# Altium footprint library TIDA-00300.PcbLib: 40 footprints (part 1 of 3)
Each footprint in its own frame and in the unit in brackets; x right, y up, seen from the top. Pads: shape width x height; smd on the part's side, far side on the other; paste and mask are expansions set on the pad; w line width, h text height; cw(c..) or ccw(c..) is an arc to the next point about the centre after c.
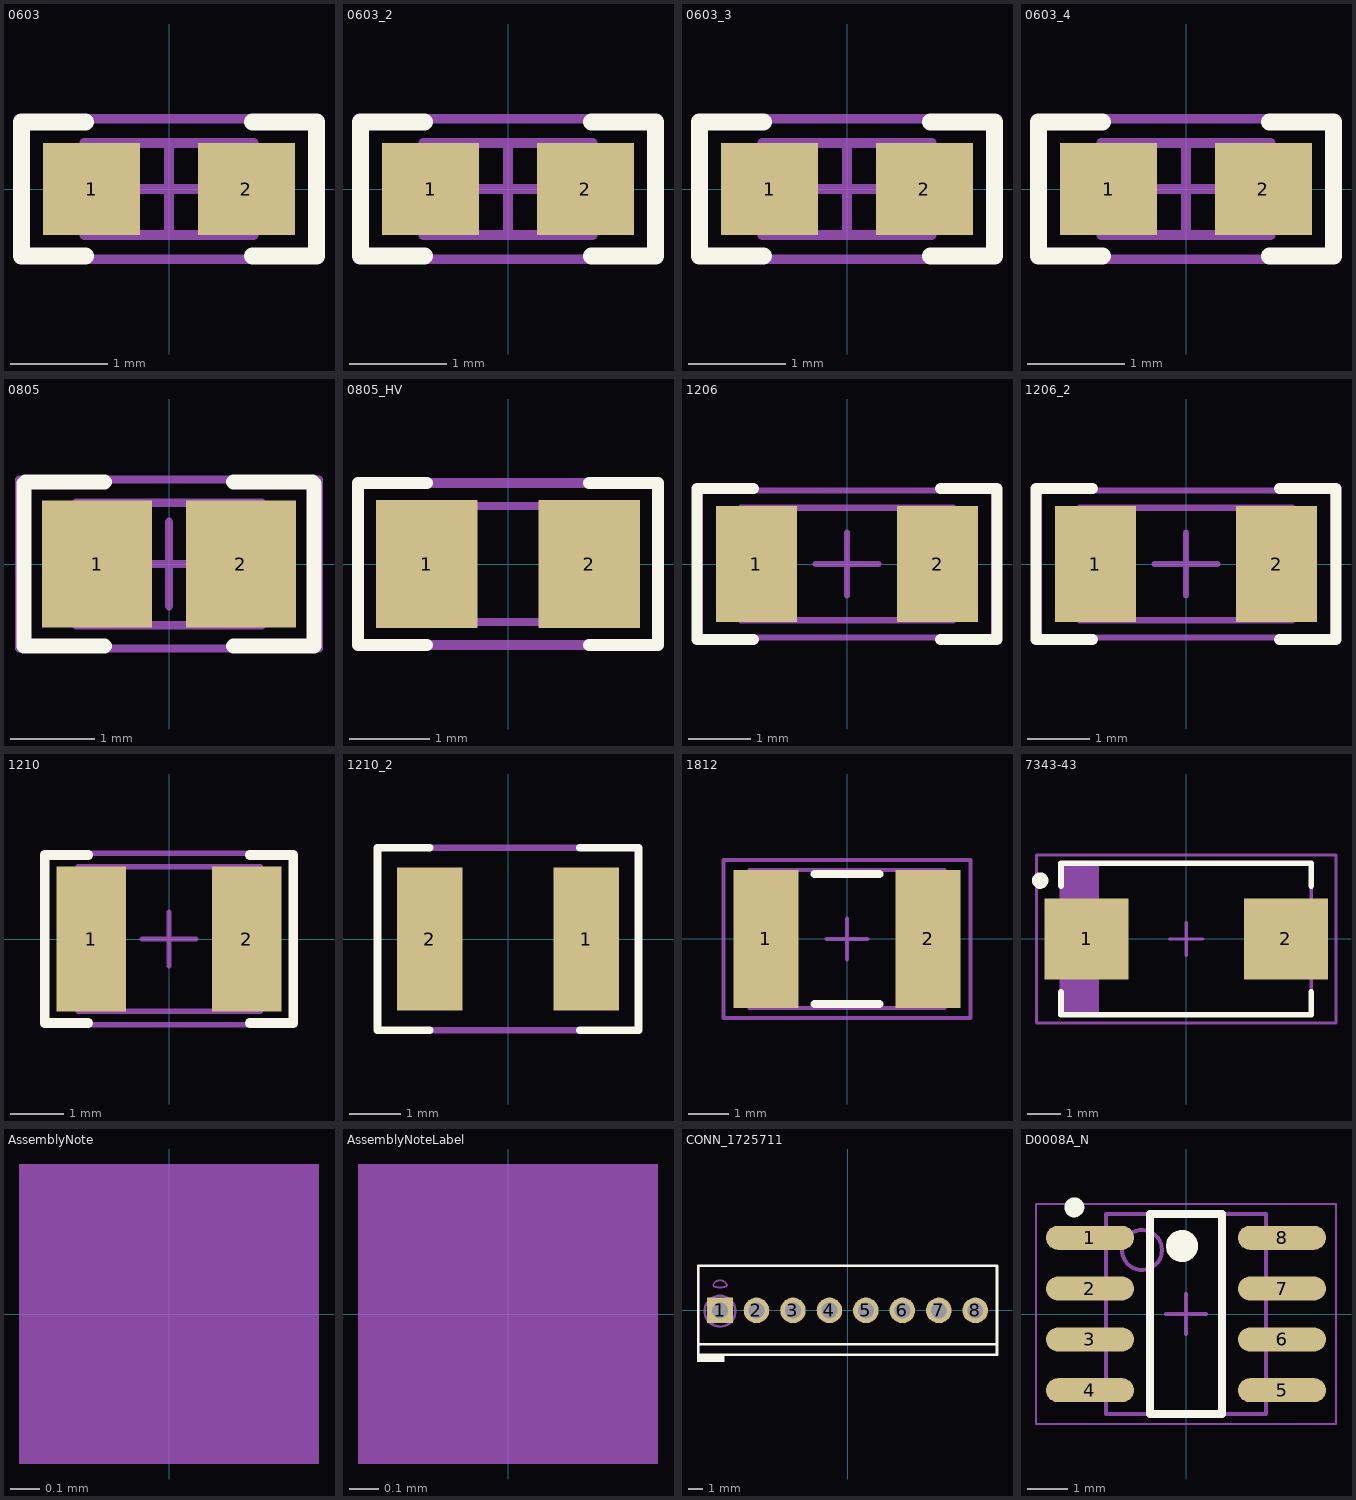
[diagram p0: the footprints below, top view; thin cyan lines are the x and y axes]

## 0603 [mm] "0603 from SM-752 data"
height 0.85
pads (2):
  rect 1x0.95 smd: 1(-0.8,0) 2(0.8,0)
Top Overlay:
  lines w0.178: -0.864,-0.691 -1.524,-0.691 -1.524,0.693 -0.864,0.693 ; 0.864,-0.691 1.524,-0.691 1.524,0.693 0.864,0.693
Mechanical 5:
  lines w0.1: -1.55,-0.725 1.55,-0.725 1.55,0.725 -1.55,0.725 -1.55,-0.725
  text ".Designator" at -1.067,-0.33 h0.76
Mechanical 13:
  lines w0.1: -0.55,-0.475 -0.55,0.475 ; 0.55,-0.475 0.55,0.475 ; -0.875,-0.475 -0.875,0.475 0.875,0.475 0.875,-0.475 -0.875,-0.475
Mechanical 15:
  lines w0.1: -0.475,0 0.475,0 ; 0,-0.475 0,0.475 ; -1.55,-0.725 -1.55,0.725 1.55,0.725 1.55,-0.725 -1.55,-0.725
3D body: height 0.85, standoff 0, extent 0.551,-0.474 0.874,0.474
3D body: height 0.85, standoff 0, extent -0.549,-0.474 0.549,0.474
3D body: height 0.85, standoff 0, extent -0.874,-0.474 -0.551,0.474

## 0603_2 [mm]
pads (2):
  rect 1x0.95 smd: 1(-0.8,0) 2(0.8,0)
Top Overlay:
  lines w0.178: -0.864,-0.691 -1.524,-0.691 -1.524,0.693 -0.864,0.693 ; 0.864,-0.691 1.524,-0.691 1.524,0.693 0.864,0.693
Mechanical 5:
  lines w0.1: -1.55,-0.725 -1.55,0.725 1.55,0.725 1.55,-0.725 -1.55,-0.725
  text ".Designator" at 0.914,0.406 h0.76
Mechanical 13:
  lines w0.1: -0.55,-0.475 -0.55,0.475 ; 0.55,-0.475 0.55,0.475 ; -0.875,-0.475 0.875,-0.475 0.875,0.475 -0.875,0.475 -0.875,-0.475
Mechanical 15:
  lines w0.1: -0.475,0 0.475,0 ; 0,-0.475 0,0.475 ; -1.55,-0.725 1.55,-0.725 1.55,0.725 -1.55,0.725 -1.55,-0.725
3D body: height 0.85, standoff 0, extent -0.874,-0.474 -0.551,0.474
3D body: height 0.85, standoff 0, extent -0.549,-0.474 0.549,0.474
3D body: height 0.85, standoff 0, extent 0.551,-0.474 0.874,0.474

## 0603_3 [mm]
pads (2):
  rect 1x0.95 smd: 1(-0.8,0) 2(0.8,0)
Top Overlay:
  lines w0.178: -0.864,-0.691 -1.524,-0.691 -1.524,0.693 -0.864,0.693 ; 0.864,-0.691 1.524,-0.691 1.524,0.693 0.864,0.693
Mechanical 5:
  lines w0.1: -1.55,-0.725 1.55,-0.725 1.55,0.725 -1.55,0.725 -1.55,-0.725
  text ".Designator" at -1.143,-0.381 h0.76
Mechanical 13:
  lines w0.1: -0.55,-0.475 -0.55,0.475 ; 0.55,-0.475 0.55,0.475 ; -0.875,-0.475 -0.875,0.475 0.875,0.475 0.875,-0.475 -0.875,-0.475
Mechanical 15:
  lines w0.1: -0.475,0 0.475,0 ; 0,-0.475 0,0.475 ; -1.55,-0.725 -1.55,0.725 1.55,0.725 1.55,-0.725 -1.55,-0.725
3D body: height 0.85, standoff 0, extent 0.551,-0.474 0.874,0.474
3D body: height 0.85, standoff 0, extent -0.549,-0.474 0.549,0.474
3D body: height 0.85, standoff 0, extent -0.874,-0.474 -0.551,0.474

## 0603_4 [mm]
pads (2):
  rect 1x0.95 smd: 1(-0.8,0) 2(0.8,0)
Top Overlay:
  lines w0.178: -0.864,-0.691 -1.524,-0.691 -1.524,0.693 -0.864,0.693 ; 0.864,-0.691 1.524,-0.691 1.524,0.693 0.864,0.693
Mechanical 5:
  lines w0.1: -1.55,-0.725 -1.55,0.725 1.55,0.725 1.55,-0.725 -1.55,-0.725
  text ".Designator" at -1.016,-0.356 h0.76
Mechanical 13:
  lines w0.1: -0.55,-0.475 -0.55,0.475 ; 0.55,-0.475 0.55,0.475 ; -0.875,-0.475 0.875,-0.475 0.875,0.475 -0.875,0.475 -0.875,-0.475
Mechanical 15:
  lines w0.1: -0.475,0 0.475,0 ; 0,-0.475 0,0.475 ; -1.55,-0.725 1.55,-0.725 1.55,0.725 -1.55,0.725 -1.55,-0.725
3D body: height 0.85, standoff 0, extent -0.874,-0.474 -0.551,0.474
3D body: height 0.85, standoff 0, extent -0.549,-0.474 0.549,0.474
3D body: height 0.85, standoff 0, extent 0.551,-0.474 0.874,0.474

## 0805 [mm] "0805 from SM-752 data"
height 1.1
pads (2):
  rect 1.3x1.5 smd: 1(-0.85,0) 2(0.85,0)
Top Overlay:
  lines w0.178: -0.762,-0.968 -1.717,-0.968 -1.717,0.95 -1.699,0.968 -0.762,0.968 ; 0.762,-0.968 1.717,-0.968 1.717,0.95 1.699,0.968 0.762,0.968
Mechanical 5:
  lines w0.1: -1.775,-1 -1.775,1 1.775,1 1.775,-1 -1.775,-1
  text ".Designator" at -1.143,-0.381 h0.76
Mechanical 13:
  lines w0.1: -0.65,-0.725 -0.65,0.725 ; 0.65,-0.725 0.65,0.725 ; -1.1,-0.725 -1.1,0.725 1.1,0.725 1.1,-0.725 -1.1,-0.725
Mechanical 15:
  lines w0.1: -0.5,0 0.5,0 ; 0,-0.5 0,0.5 ; -1.775,-1 -1.775,1 1.775,1 1.775,-1 -1.775,-1
3D body: height 1.1, standoff 0, extent 0.651,-0.724 1.099,0.724
3D body: height 1.1, standoff 0, extent -0.649,-0.724 0.649,0.724
3D body: height 1.1, standoff 0, extent -1.099,-0.724 -0.651,0.724

## 0805_HV [mil] "0805 with 30mil clearance between pads"
height 43.31
pads (2):
  rect 50x63 smd: 1(-40,0) 2(40,0)
Top Overlay:
  lines w6: -40,-40 -74,-40 -74,0 -74,40 -40,40 ; 40,-40 74,-40 74,0 74,40 40,40
Mechanical 5:
  lines w5: -74,-40 74,-40 74,40 -74,40 -74,-40
  text ".Designator" at -38,-18 h30
Mechanical 13:
  lines w3.94: -25.59,-28.54 -25.59,28.54 ; 25.59,-28.54 25.59,28.54 ; -43.31,-28.54 -43.31,28.54 43.31,28.54 43.31,-28.54 -43.31,-28.54
3D body: height 43.31, standoff 0, extent 25.61,-28.52 43.29,28.52
3D body: height 43.31, standoff 0, extent -25.57,-28.52 25.57,28.52
3D body: height 43.31, standoff 0, extent -43.29,-28.52 -25.61,28.52

## 1206 [mm] "1206 from SM-752 data"
height 1.35
pads (2):
  rect 1.3x1.85 smd: 1(-1.45,0) 2(1.45,0)
Top Overlay:
  lines w0.178: -1.5,-1.21 -2.4,-1.21 -2.4,1.21 -1.5,1.21 ; 1.5,-1.21 2.4,-1.21 2.4,1.21 1.5,1.21
Mechanical 5:
  lines w0.1: -1.7,-0.9 1.7,-0.9 1.7,0.9 -1.7,0.9 -1.7,-0.9
  text ".Designator" at 1.194,0.305 h0.76
Mechanical 13:
  lines w0.1: -1.2,-0.9 -1.2,0.9 ; 1.2,-0.9 1.2,0.9 ; -1.7,-0.9 1.7,-0.9 1.7,0.9 -1.7,0.9 -1.7,-0.9
Mechanical 15:
  lines w0.1: -0.5,0 0.5,0 ; 0,-0.5 0,0.5 ; -2.35,-1.175 2.35,-1.175 2.35,1.175 -2.35,1.175 -2.35,-1.175
3D body: height 1.35, standoff 0, extent -1.699,-0.899 -1.201,0.899
3D body: height 1.35, standoff 0, extent -1.199,-0.899 1.199,0.899
3D body: height 1.35, standoff 0, extent 1.201,-0.899 1.699,0.899

## 1206_2 [mm]
pads (2):
  rect 1.3x1.85 smd: 1(-1.45,0) 2(1.45,0)
Top Overlay:
  lines w0.178: -1.5,-1.21 -2.4,-1.21 -2.4,1.21 -1.5,1.21 ; 1.5,-1.21 2.4,-1.21 2.4,1.21 1.5,1.21
Mechanical 5:
  lines w0.1: -1.7,-0.9 1.7,-0.9 1.7,0.9 -1.7,0.9 -1.7,-0.9
  text ".Designator" at -0.635,-0.406 h0.81
Mechanical 13:
  lines w0.1: -1.2,-0.9 -1.2,0.9 ; 1.2,-0.9 1.2,0.9 ; -1.7,-0.9 1.7,-0.9 1.7,0.9 -1.7,0.9 -1.7,-0.9
Mechanical 15:
  lines w0.1: -0.5,0 0.5,0 ; 0,-0.5 0,0.5 ; -2.35,-1.175 2.35,-1.175 2.35,1.175 -2.35,1.175 -2.35,-1.175
3D body: height 1.35, standoff 0, extent -1.699,-0.899 -1.201,0.899
3D body: height 1.35, standoff 0, extent -1.199,-0.899 1.199,0.899
3D body: height 1.35, standoff 0, extent 1.201,-0.899 1.699,0.899

## 1210 [mm] "1210 from SM-752 data"
height 1.35
pads (2):
  rect 1.3x2.7 smd: 1(-1.45,0) 2(1.45,0)
Top Overlay:
  lines w0.178: -1.511,-1.568 -2.316,-1.568 -2.316,1.568 -1.511,1.568 ; 1.511,-1.568 2.316,-1.568 2.316,1.568 1.511,1.568
Mechanical 5:
  lines w0.1: -1.7,-1.35 -1.7,1.35 1.7,1.35 1.7,-1.35 -1.7,-1.35
  text ".Designator" at -0.584,-0.305 h0.76
Mechanical 13:
  lines w0.1: -1.2,-1.35 -1.2,1.35 ; 1.2,-1.35 1.2,1.35 ; -1.7,-1.35 1.7,-1.35 1.7,1.35 -1.7,1.35 -1.7,-1.35
Mechanical 15:
  lines w0.1: -0.5,0 0.5,0 ; 0,-0.5 0,0.5 ; -2.35,-1.6 2.35,-1.6 2.35,1.6 -2.35,1.6 -2.35,-1.6
3D body: height 1.35, standoff 0, extent 1.201,-1.349 1.699,1.349
3D body: height 1.35, standoff 0, extent -1.199,-1.349 1.199,1.349
3D body: height 1.35, standoff 0, extent -1.699,-1.349 -1.201,1.349

## 1210_2 [mil]
pads (2):
  rect 50x110 smd: 1(60,0) 2(-60,0)
Top Overlay:
  lines w6: -60,-70 -100,-70 -100,70 -60,70 ; 55,-70 100,-70 100,70 55,70
Mechanical 5:
  lines w5: -100,-70 100,-70 100,70 -100,70 -100,-70
  text ".Designator" at 40,20 h30

## 1812 [mm]
height 1.35
pads (2):
  rect 1.6x3.4 smd: 1(-2,0) 2(2,0)
Top Overlay:
  lines w0.2: -0.8,-1.6 0.8,-1.6 ; -0.8,1.6 0.8,1.6
Mechanical 5:
  lines w0.1: -2.4,-1.7 -2.4,1.7 2.4,1.7 2.4,-1.7 -2.4,-1.7
  text ".Designator" at 0.889,0.635 h1.02
Mechanical 13:
  lines w0.1: -1.9,-1.7 -1.9,1.7 ; 1.9,-1.7 1.9,1.7 ; -2.4,-1.7 2.4,-1.7 2.4,1.7 -2.4,1.7 -2.4,-1.7
Mechanical 15:
  lines w0.1: -0.5,0 0.5,0 ; 0,-0.5 0,0.5 ; -3.05,-1.95 3.05,-1.95 3.05,1.95 -3.05,1.95 -3.05,-1.95
3D body: height 1.35, standoff 0, extent 1.901,-1.699 2.399,1.699
3D body: height 1.35, standoff 0, extent -1.899,-1.699 1.899,1.699
3D body: height 1.35, standoff 0, extent -2.399,-1.699 -1.901,1.699

## 7343-43 [mm] "Medium density IPC based on Kemet T495 series"
height 4.3
pads (2):
  rect 2.55x2.45 smd: 1(-3.025,0) 2(3.025,0)
Top Overlay:
  circle w0.25: c-4.439,1.775 r0.125
  lines w0.178: -3.8,-1.614 -3.8,-2.3 3.8,-2.3 3.8,-1.614 ; -3.8,1.614 -3.8,2.3 3.8,2.3 3.8,1.614
Mechanical 5:
  rectangle: -3.8,-2.3 -2.7,2.3
  lines w0.1: -2.7,-2.3 -2.7,2.3 ; -3.8,-2.3 -3.8,2.3 3.8,2.3 3.8,-2.3 -3.8,-2.3
  text ".Designator" at -1.194,-0.457 h1.02
Mechanical 15:
  lines w0.1: -0.5,0 0.5,0 ; 0,-0.5 0,0.5 ; -4.55,-2.55 -4.55,2.55 4.55,2.55 4.55,-2.55 -4.55,-2.55
3D body: height 4.3, standoff 4.3, extent -3.799,-2.299 -2.701,2.299
3D body: height 4.3, standoff 0, extent -3.8,-2.3 3.8,2.3

## AssemblyNote [mm] "Assembly Note"
Mechanical 5:
  rectangle: -0.508,-0.508 0.508,0.508
  text ".Comment" at 1.143,-0.508 h0.76
  text ".Designator" at -4.191,-0.508 h0.76

## AssemblyNoteLabel [mm] "Assembly Note for PCB Labels"
Mechanical 5:
  rectangle: -0.508,-0.508 0.508,0.508
  text "Install label in silkscreened box after final wash.  Text shall be 8 pt font.  Text shall be per the Label Table in the PDF schematic." at 1.651,-0.457 h0.76
  text ".Designator" at -3.683,-0.457 h0.76

## CONN_1725711 [mm] "Phoenix Contact"
height 13.8
pads (8):
  rect 1.78x1.78 hole 1.1: 1(-8.89,0)
  round 1.78 hole 1.1: 2(-6.35,0) 3(-3.81,0) 4(-1.27,0) 5(1.27,0) 6(3.81,0) 7(6.35,0) 8(8.89,0)
Top Overlay:
  rectangle: -10.493,-3.6 -8.588,-3.1
  lines w0.178: -10.39,-2.361 10.39,-2.361 ; -10.404,-3.1 10.4,-3.1 10.4,3.1 -10.398,3.1 -10.404,-3.1
Mechanical 5:
  lines w0.127: -10.39,-2.361 -10.39,-2.8 -10.39,-3.1 10.39,-3.1 10.39,-2.8 10.39,-2.361 ; -10.39,-2.361 -10.39,-1.51 -10.39,-1.22 -10.39,1.132 -10.39,1.417 -10.39,3.1 10.39,3.1 10.39,1.417 10.39,1.132 10.39,-1.22 10.39,-1.51 10.39,-2.361 ; -10.39,-2.361 10.39,-2.361 ; -9.788,-0.594 cw(c-8.89,-0.05) -8.89,1 cw(c-8.89,-0.05) -8.346,0.848 ; -9.788,-0.594 ccw(c-8.89,-0.05) -9.434,-0.948 ; -9.788,-0.594 -9.4,-0.206 -8.89,0.304 -8.684,0.51 -8.346,0.848 ; -9.434,-0.948 ccw(c-8.89,-0.05) -8.89,-1.1 ccw(c-8.89,-0.05) -7.992,0.494 ; -9.434,-0.948 -9.021,-0.534 -8.89,-0.403 -8.356,0.131 -7.992,0.494 ; -8.346,0.848 cw(c-8.89,-0.05) -7.992,0.494 ; -9.365,1.741 -9.363,1.733 -9.361,1.726 -9.357,1.719 -9.351,1.711 -9.345,1.704 -9.338,1.697 -9.329,1.691 -9.319,1.684 -9.309,1.677 -9.297,1.671 -9.284,1.665 -9.27,1.659 -9.255,1.653 -9.24,1.647 -9.223,1.642 -9.206,1.637 -9.188,1.632 -9.169,1.628 -9.149,1.624 -9.129,1.62 -9.108,1.616 -9.087,1.613 -9.065,1.61 -9.042,1.608 -9.02,1.606 -8.997,1.604 -8.973,1.602 -8.95,1.601 -8.926,1.6 -8.89,1.6 -8.866,1.6 -8.842,1.601 -8.819,1.602 -8.795,1.603 -8.772,1.605 -8.749,1.607 -8.727,1.609 -8.705,1.612 -8.683,1.615 -8.662,1.618 -8.641,1.622 -8.621,1.626 -8.602,1.63 -8.584,1.635 -8.566,1.639 -8.549,1.645 -8.533,1.65 -8.517,1.656 -8.503,1.662 -8.49,1.668 -8.477,1.674 -8.466,1.68 -8.456,1.687 -8.447,1.694 -8.439,1.701 -8.432,1.708 -8.426,1.715 -8.421,1.722 -8.418,1.729 -8.416,1.737 -8.415,1.744 -8.415,1.751 -8.417,1.763 ccw(c-8.89,1.6) -8.89,2.1 ccw(c-8.89,1.6) -9.363,1.763 -9.365,1.755 -9.365,1.748 -9.365,1.741 ; -8.89,-1.15 cw(c-8.89,-0.05) -8.89,1.05 cw(c-8.89,-0.05) -8.89,-1.15
  text ".Designator" at -10.744,-0.94 h1.02
3D body "PhoenixContact_1725711.stp": height 8.52, standoff -3.48, extent -10.39,-3.1 10.39,3.1

## D0008A_N [mm] "SOIC, 8-Leads, Body 4.9x3.9mm, Pitch 1.27mm, IPC Medium Density"
height 1.75
pads (8):
  oval 2.2x0.6 smd: 1(-2.4,1.905) 2(-2.4,0.635) 3(-2.4,-0.635) 4(-2.4,-1.905) 5(2.4,-1.905) 6(2.4,-0.635) 7(2.4,0.635) 8(2.4,1.905)
Top Overlay:
  circle w0.4: c-0.1,1.7 r0.2
  circle w0.25: c-2.792,2.667 r0.125
  lines w0.2: -0.9,-2.5 0.9,-2.5 0.9,2.5 -0.9,2.5 -0.9,-2.5
Mechanical 5:
  circle w0.1: c-1.1,1.6 r0.5
  lines w0.1: -2,-2.5 2,-2.5 2,2.5 -2,2.5 -2,-2.5
  text ".Designator" at -0.977,-0.344 h0.76
Mechanical 15:
  lines w0.05: -3.75,-2.75 3.75,-2.75 3.75,2.75 -3.75,2.75 -3.75,-2.75
  lines w0.1: -0.5,0 0.5,0 ; 0,-0.5 0,0.5
3D body: height 1.75, standoff 0.1, extent -2,-2.5 2,2.5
